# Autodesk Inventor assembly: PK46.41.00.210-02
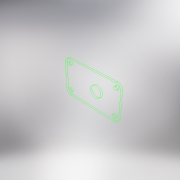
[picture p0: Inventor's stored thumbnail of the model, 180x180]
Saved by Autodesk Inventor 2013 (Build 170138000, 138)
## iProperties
Created: 2012-02
Part Number: PK46.41.00.210-02
Document SubType Name: Weldment
Designer: tedescj
Weld Material: Welded Aluminum-6061
Author: tedescj
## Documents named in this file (5)
- C:\Product Design Suite 2013 Test Drive\Dynamic Simulation\Workspace\Assy, Chassis, Front\PK46.41.00.210-02.iam
- C:\Product Design Suite 2013 Test Drive\Dynamic Simulation\Workspace\Assy, Chassis, Front\PK46.41.00.0111.ipt
- C:\Product Design Suite 2013 Test Drive\Dynamic Simulation\Workspace\Assy, Chassis, Front\PK46.41.00.012-02.ipt
- C:\Product Design Suite 2013 Test Drive\Dynamic Simulation\Workspace\Assy, Chassis, Front\PK46.41.00.011-02.ipt
- C:\Product Design Suite 2013 Test Drive\Dynamic Simulation\Workspace\Assy, Chassis, Front\PK46.41.00.013.ipt
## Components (4 placed, 4 different names)
1. PK46.41.00.0111:1 — Mate:2
2. PK46.41.00.012-02:1
3. PK46.41.00.011-02:1
4. PK46.41.00.013:1 — Flush:1, Mate:1, Mate:2
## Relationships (3: Mate 2, Flush 1)
- Flush:1: PK46.41.00.013:1
- Mate:1: PK46.41.00.013:1
- Mate:2: PK46.41.00.0111:1 ↔ PK46.41.00.013:1
